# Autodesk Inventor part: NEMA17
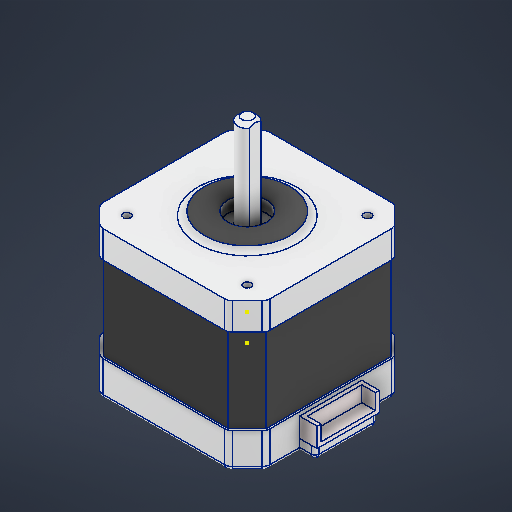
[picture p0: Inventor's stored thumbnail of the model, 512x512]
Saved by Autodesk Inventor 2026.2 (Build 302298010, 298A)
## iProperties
Created: 2025-09
Part Number: NEMA17
Material: 강철, 아연도금
Document SubType Name: Modeling
Designer: work
Density: 7.85 g/cm^3
Appearance: 알루미늄 - 평지
Author: work
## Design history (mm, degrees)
sketch "스케치1"
  geometry: L1 (0, 0)-(43, 0); L2 (43, 0)-(43, -43); L3 (43, -43)-(0, -43); L4 (0, -43)-(0, 0)
  constraints: 8 end point, 2 parallel, 1 horizontal, 1 perpendicular
  dimensions: "d0" = 43 distance of L2.end L3.end; "d1" = 43 distance of L1.end L2.end
extrude "돌출1" new body sketch "스케치1" distance "d2" = 9; taper "d3" = 0 deg
chamfer "모따기1" distance "d4" = 5; stored, may be unused: second distance "d5" = 2, angle "d6" = 45 deg
sketch "스케치2"
  geometry: L1 (-6.828, 0)-(-36.172, 0); L2 (-43, 6.828)-(-43, 36.172); L3 (-36.172, 43)-(-6.828, 43); L4 (0, 36.172)-(0, 6.828); L5 (-37.586, 0.586)-(-42.414, 5.414); L6 (-42.414, 37.586)-(-37.586, 42.414); L7 (-5.414, 42.414)-(-0.586, 37.586); L8 (-5.414, 0.586)-(-0.586, 5.414); A1 r 2 centre (-6.828, 2) between (-6.828, 0) and (-5.414, 0.586); A2 r 2 centre (-2, 6.828) between (-0.586, 5.414) and (0, 6.828); A3 r 2 centre (-2, 36.172) between (0, 36.172) and (-0.586, 37.586); A4 r 2 centre (-6.828, 41) between (-5.414, 42.414) and (-6.828, 43); A5 r 2 centre (-36.172, 41) between (-36.172, 43) and (-37.586, 42.414); A6 r 2 centre (-41, 36.172) between (-42.414, 37.586) and (-43, 36.172); A7 r 2 centre (-41, 6.828) between (-43, 6.828) and (-42.414, 5.414); A8 r 2 centre (-36.172, 2) between (-37.586, 0.586) and (-36.172, 0); 12 further points
  constraints: 24 point on line, 16 end point, 16 point on circle, 16 tangent, 8 centre point, 7 equal radius, 2 parallel, 1 horizontal, 1 perpendicular
  dimensions: "d7" = 43 distance of point (-43, 43) point (0, 43); "d8" = 43 distance of point (-43, 0) point (-43, 43); "d9" = 6 distance of point (-37, 0) point (-43, 0); "d10" = 6 distance of point (-43, 6) point (-43, 0) (= d9); "d11" = 6 distance of point (-43, 37) point (-43, 43) (= d9); "d12" = 6 distance of point (-37, 43) point (-43, 43) (= d11); "d13" = 6 distance of point (-6, 43) point (0, 43) (= d9); "d14" = 6 distance of point (0, 37) point (0, 43) (= d13); "d15" = 6 distance of point (-6, 0) point (0, 0) (= d9); "d16" = 6 distance of point (0, 6) point (0, 0) (= d15); "d17" = 2 radius of A1
extrude "돌출2" join sketch "스케치2" distance "d18" = 22; taper "d19" = 0 deg
sketch "스케치3"
  geometry: 1 further point
sketch "스케치4"
  geometry: L1 (0, 0)-(-43, 0); L2 (-43, 0)-(-43, 43); L3 (-43, 43)-(0, 43); L4 (0, 43)-(0, 0)
  constraints: 8 end point, 2 parallel, 1 horizontal, 1 perpendicular
  dimensions: "d20" = 43 distance of L2.end L3.end; "d21" = 43 distance of L1.end L2.end
extrude "돌출3" join sketch "스케치4" distance "d22" = 7; taper "d23" = 0 deg
chamfer "모따기2" distance "d24" = 5; stored, may be unused: second distance "d25" = 2, angle "d26" = 45 deg
sketch "스케치5"
  geometry: L1 (-5, 43)-(-38, 43) reference; L2 (0, 5)-(0, 38) reference; L3 (-19.5, 23)-(-19.5, 20); A1 r 2.5 centre (-21.5, 21.5) between (-19.5, 23) and (-19.5, 20); 1 further point
  constraints: 2 end point, 2 point on circle, 1 centre point, 1 vertical
  dimensions: "d27" = 5 diameter of A1; "d28" = 21.5 distance from line of L1 A1.centre; "d29" = 21.5 distance from line of L2 A1.centre; "d30" = 4.5 dimension on A1 L3
extrude "돌출4" join sketch "스케치5" distance "d31" = 22.2; taper "d32" = 0 deg
sketch "스케치6"
  geometry: C1 r 3.5 at (-21.5, -21.5); A1 r 2.5 centre (-21.5, -21.5) between (-19.5, -20) and (-19.5, -23) reference; 1 further point
  constraints: 1 centre point, 1 coincident
  dimensions: "d33" = 7 diameter of C1
extrude "돌출5" cut sketch "스케치6" distance "d34" = 3.5; taper "d35" = 0 deg
sketch "스케치7"
  geometry: L1 (0, -5)-(0, -38) reference; L2 (0, -13.5)-(4, -13.5); L3 (4, -13.5)-(4, -29.5); L4 (4, -29.5)-(0, -29.5); L5 (0, -29.5)-(0, -13.5); 3 further points
  constraints: 8 end point, 2 midpoint, 2 parallel, 1 horizontal, 1 perpendicular, 1 point on line
  dimensions: "d36" = 4 distance of L3.end L4.end; "d37" = 16 distance of L2.end L3.end
extrude "돌출6" join sketch "스케치7" distance "d38" = 3; taper "d39" = 0 deg
sketch "스케치8"
  geometry: L1 (0, 13.5)-(0, 29.5) reference; L2 (0, 13.5)-(4.5, 13.5); L3 (4.5, 13.5)-(4.5, 29.5); L4 (4.5, 29.5)-(0, 29.5); L5 (0, 29.5)-(0, 13.5); 2 further points
  constraints: 8 end point, 2 parallel, 1 horizontal, 1 perpendicular
  dimensions: "d40" = 4.5 distance of L4.end L3.end
extrude "돌출7" new body sketch "스케치8" distance "d41" = 5; taper "d42" = 0 deg
feature "쉘1" dims "d43" = 1
sketch "스케치9"
  geometry: C1 r 11 at (-21.5, 21.5); A1 r 2.5 centre (-21.5, 21.5) between (-19.5, 23) and (-19.5, 20) reference; 1 further point
  constraints: 1 centre point, 1 coincident
  dimensions: "d44" = 22 diameter of C1
extrude "돌출8" join sketch "스케치9" distance "d45" = 1; taper "d46" = 0 deg
sketch "스케치10"
  geometry: L1 (2, -1.5)-(2, 1.5) reference; C1 r 5 at (0, 0); A1 r 2.5 centre (0, 0) between (2, 1.5) and (2, -1.5) reference; A2 r 2.5 centre (0, 0) between (2, 1.5) and (2, -1.5) reference; 3 further points
  constraints: 1 centre point, 1 coincident
  dimensions: "d47" = 10 diameter of C1
extrude "돌출9" cut sketch "스케치10" distance "d48" = 3; taper "d49" = 0 deg
sketch "스케치11"
  geometry: 1 further point
sketch "스케치12"
  geometry: C1 r 5 at (0, 0) reference; C2 r 2.5 at (0, 0); 1 further point
  constraints: 1 centre point, 1 coincident
extrude "돌출10" join sketch "스케치12" distance "d50" = 1; taper "d51" = 0 deg
sketch "스케치13"
  geometry: L1 (0, 5)-(0, 38) reference; L2 (-38, 0)-(-5, 0) reference; L3 (-43, 38)-(-38, 43) reference; L4 (-43, 38)-(-43, 5) reference; L5 (-38, 0)-(-43, 5) reference; L6 (-38, 0)-(-5, 0) reference; L7 (0, 5)-(-5, 0) reference; L8 (0, 5)-(0, 38) reference; L9 (-5, 43)-(0, 38) reference; L10 (-5, 43)-(-38, 43) reference; L11 (-19.5, 20)-(-19.5, 23) reference; L12 (-37, 6)-(-6, 6); L13 (-6, 6)-(-6, 37); L14 (-6, 37)-(-37, 37); L15 (-37, 37)-(-37, 6); L16 (-37, 6)-(-6, 37); L17 (-6, 6)-(-37, 37); C1 r 1 at (-6, 6); C2 r 11 at (-21.5, 21.5) reference; C3 r 1 at (-6, 37); C4 r 1 at (-37, 37); C5 r 1 at (-37, 6); C6 r 5 at (-21.5, 21.5) reference; A1 r 2.5 centre (-21.5, 21.5) between (-19.5, 23) and (-19.5, 20) reference; 1 further point
  constraints: 12 end point, 4 centre point, 2 midpoint, 2 parallel, 1 coincident, 1 horizontal, 1 perpendicular, 9 other
  dimensions: "d52" = 2 diameter of C1; "d57" = 360 deg dimension on C2.centre C1.centre (derived); "d72" = 31 distance of L14.end L13.end; "d73" = 31 distance of L13.end L12.end
extrude "돌출11" cut sketch "스케치13" distance "d59" = 5; taper "d60" = 0 deg
sketch "스케치14"
  geometry: L1 (-5, 43)-(-38, 43) reference; L2 (-21.5, 43)-(-21.5, 0); L3 (-43, 38)-(-43, 5) reference; L4 (-43, 21.5)-(0, 21.5); L5 (0, 13.5)-(0, 29.5) reference; L6 (-43, 43)-(0, 43); L7 (0, 43)-(0, 0); L8 (0, 0)-(-43, 0); L9 (-43, 0)-(-43, 43); L10 (-43, 43)-(0, 0); L11 (0, 43)-(-43, 0); L12 (-42.5, 42.5)-(-0.5, 42.5); L13 (-0.5, 42.5)-(-0.5, 0.5); L14 (-0.5, 0.5)-(-42.5, 0.5); L15 (-42.5, 0.5)-(-42.5, 42.5); L16 (-42.5, 42.5)-(-0.5, 0.5); L17 (-0.5, 42.5)-(-42.5, 0.5); C1 r 2.5 at (-21.5, 21.5) reference; C2 r 3.5 at (-21.5, 21.5) reference; 7 further points
  constraints: 28 end point, 7 midpoint, 4 parallel, 2 horizontal, 2 perpendicular, 1 vertical
  dimensions: "d61" = 43 distance of L7.end L8.end; "d62" = 43 distance of L6.end L7.end; "d63" = 42 distance of L13.end L14.end; "d64" = 42 distance of L12.end L13.end
extrude "돌출12" cut sketch "스케치14" stored distance "d65" = 5; taper "d66" = 0 deg
fillet "모깎기1" dims "d67" = 2
chamfer "모따기3" distance "d68" = 1; stored, may be unused: second distance "d69" = 2, angle "d70" = 45 deg
fillet "모깎기2" dims "d71" = 1
node "솔리드1"
node "솔리드2"
node "투영된 루프1"
node "투영된 루프2"
node "스케치 - 원형 패턴1" dims "d57" = 360 deg (derived)
node "투영된 루프3"
